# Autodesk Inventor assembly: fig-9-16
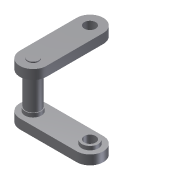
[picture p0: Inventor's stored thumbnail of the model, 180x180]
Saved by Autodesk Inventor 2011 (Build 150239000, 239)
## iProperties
Shininess: 64.0
Length Units: 11269
Angle Units: 11279
Time Units: 11290
Mass Units: 11283
Length Display Precision: 3
Angle Display Precision: 2
Created: 2002-01
Part Number: fig-9-16
Document SubType Name: Assembly
Designer: ***
Density: 0.0
Volumn: 0.0
Area: 0.0
PropertySet Name: Model Information
Control State: 0
Master: False
Checked Out: False
Author: ***
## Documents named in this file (3)
- C:\Users\CADSoft\Desktop\part files\c09-inv-2011-prt\fig-9-16.iam
- C:\Users\CADSoft\Desktop\inventor\c09-inv-2010-prt\c09\Part5.ipt
- C:\Users\CADSoft\Desktop\inventor\c09-inv-2010-prt\c09\Part6.ipt
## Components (3 placed, 2 different names)
1. Part5:1 — Insert:1, Angle:1
2. Part6:1 — Insert:1, Insert:2
3. Part5:2 — Insert:2, Angle:1
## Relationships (3: Insert 2, Angle 1)
- Insert:1: Part5:1 ↔ Part6:1
- Insert:2: Part6:1 ↔ Part5:2
- Angle:1: Part5:1 ↔ Part5:2
